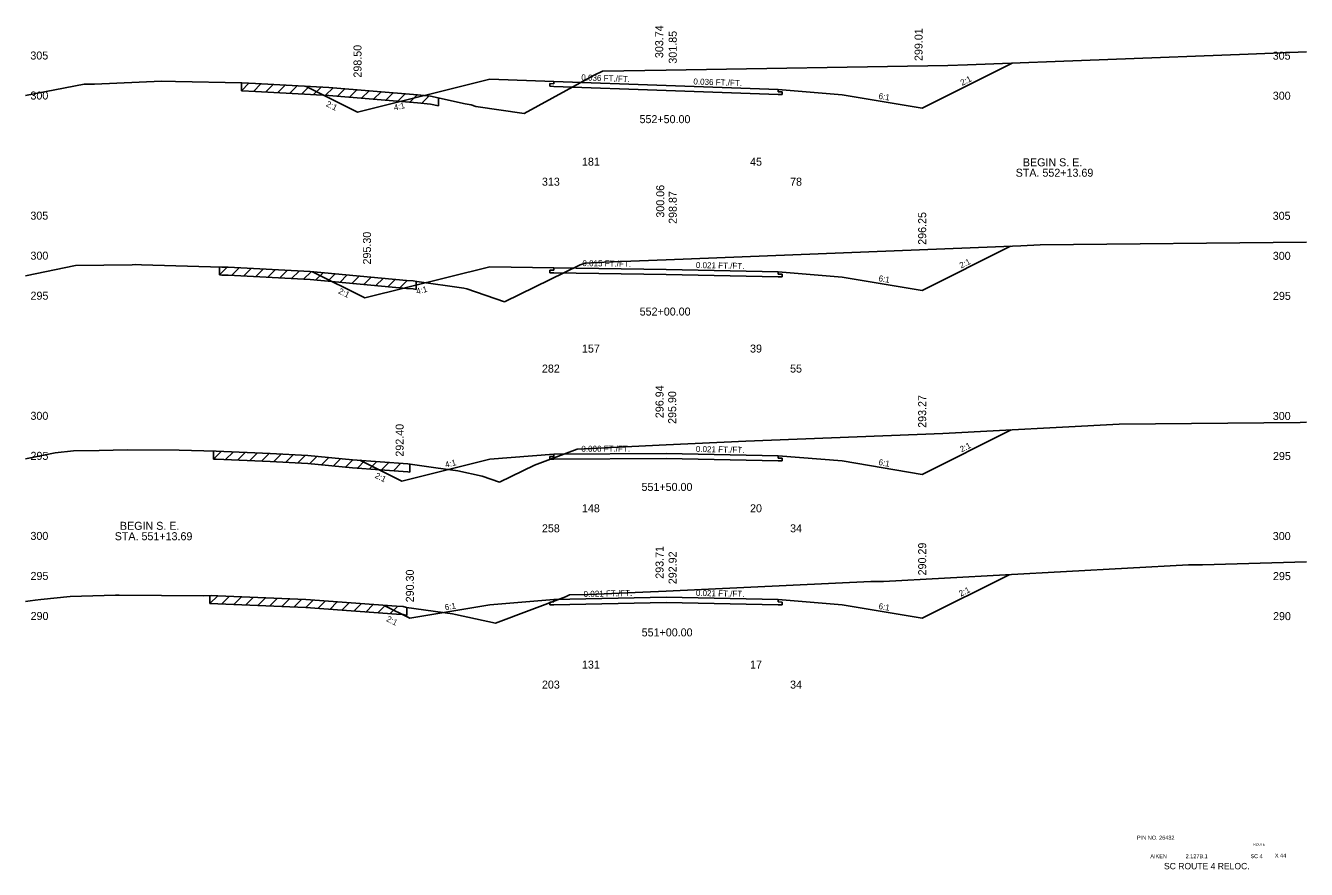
# Model space of a CAD drawing. Extents: x 2967 to 4323, y -3677 to -817.
# Drawn here: x 3555.3 to 3715.3, y -1510.9 to -1405.5 of the extents above; entities that cross this region are included whole.
import ezdxf

# ---------------------------------------------------------------- set-up
doc = ezdxf.new("R2010")
doc.units = 0
for name, color, linetype in [('Level 1', 7, 'Continuous'), ('Level 10', 7, 'Continuous'), ('Level 11', 7, 'Continuous'), ('Level 12', 7, 'Continuous'), ('Level 20', 7, 'Continuous'), ('Level 3', 7, 'Continuous'), ('Level 32', 7, 'Continuous'), ('Level 33', 7, 'Continuous'), ('Level 59', 7, 'Continuous'), ('Level 6', 7, 'Continuous'), ('Level 60', 7, 'Continuous'), ('Level 61', 7, 'Continuous'), ('Level 7', 7, 'Continuous')]:
    doc.layers.add(name, color=color, linetype=linetype)

msp = doc.modelspace()

# ---------------------------------------------------------------- linework, layer by layer
at = {"layer": 'Level 11'}
for p, q in [((3621.35, -1412.79), (3620.85, -1412.77)), ((3620.85, -1412.77), (3620.85, -1413.11)), ((3621.35, -1412.49), (3621.35, -1412.79)), ((3620.85, -1413.11), (3621.35, -1413.13)), ((3649.35, -1413.8), (3649.35, -1413.5)), ((3649.85, -1413.81), (3649.35, -1413.8)), ((3649.35, -1414.14), (3649.85, -1414.15)), ((3649.85, -1414.15), (3649.85, -1413.81)), ((3621.35, -1436.06), (3620.85, -1436.05)), ((3620.85, -1436.05), (3620.85, -1436.39)), ((3620.85, -1436.39), (3621.35, -1436.4)), ((3621.35, -1435.76), (3621.35, -1436.06)), ((3649.35, -1436.56), (3649.35, -1436.26)), ((3649.85, -1436.57), (3649.35, -1436.56)), ((3649.85, -1436.91), (3649.85, -1436.57)), ((3649.35, -1436.9), (3649.85, -1436.91)), ((3621.35, -1459.03), (3621.35, -1459.33)), ((3621.35, -1459.33), (3620.85, -1459.33)), ((3620.85, -1459.33), (3620.85, -1459.67)), ((3620.85, -1459.67), (3621.35, -1459.67)), ((3649.35, -1459.54), (3649.35, -1459.24)), ((3649.85, -1459.55), (3649.35, -1459.54)), ((3649.35, -1459.88), (3649.85, -1459.89)), ((3649.85, -1459.89), (3649.85, -1459.55)), ((3621.35, -1477.51), (3620.85, -1477.52)), ((3620.85, -1477.52), (3620.85, -1477.86)), ((3620.85, -1477.86), (3621.35, -1477.85)), ((3621.35, -1477.21), (3621.35, -1477.51)), ((3649.35, -1477.51), (3649.35, -1477.21)), ((3649.85, -1477.52), (3649.35, -1477.51)), ((3649.35, -1477.85), (3649.85, -1477.86)), ((3649.85, -1477.86), (3649.85, -1477.52))]:
    msp.add_line(p, q, dxfattribs=at)
at = {"layer": 'Level 12'}
for p, q in [((3635.35, -1413.63), (3621.35, -1413.13)), ((3649.35, -1414.14), (3635.35, -1413.63)), ((3635.35, -1436.61), (3621.35, -1436.4)), ((3649.35, -1436.9), (3635.35, -1436.61)), ((3635.35, -1459.59), (3621.35, -1459.67)), ((3649.35, -1459.88), (3635.35, -1459.59)), ((3635.35, -1477.56), (3621.35, -1477.85)), ((3649.35, -1477.85), (3635.35, -1477.56))]:
    msp.add_line(p, q, dxfattribs=at)
at = {"layer": 'Level 59'}
for p, q in [((3621.35, -1412.49), (3635.35, -1412.99)), ((3635.35, -1412.99), (3649.35, -1413.5)), ((3621.35, -1435.76), (3635.35, -1435.97)), ((3635.35, -1435.97), (3649.35, -1436.26)), ((3621.35, -1459.03), (3635.35, -1458.95)), ((3635.35, -1458.95), (3649.35, -1459.24)), ((3621.35, -1477.21), (3635.35, -1476.92)), ((3635.35, -1476.92), (3649.35, -1477.21))]:
    msp.add_line(p, q, dxfattribs=at)
at = {"layer": 'Level 6'}
for p, q in [((3613.35, -1412.2), (3621.35, -1412.49)), ((3649.35, -1413.5), (3657.35, -1414.16)), ((3613.35, -1435.64), (3621.35, -1435.76)), ((3649.35, -1436.26), (3657.35, -1436.93)), ((3613.35, -1459.69), (3621.35, -1459.03)), ((3649.35, -1459.24), (3657.35, -1459.9)), ((3613.35, -1477.88), (3621.35, -1477.21)), ((3649.35, -1477.21), (3657.35, -1477.88))]:
    msp.add_line(p, q, dxfattribs=at)
at = {"layer": 'Level 60'}
for p, q in [((3673.02, -1410.42), (3708.07, -1409.09)), ((3708.07, -1409.09), (3715.35, -1408.81)), ((3627.4, -1411.23), (3635.35, -1411.1)), ((3635.35, -1411.1), (3670.57, -1410.52)), ((3670.57, -1410.52), (3673.02, -1410.42)), ((3563.94, -1412.83), (3572.33, -1412.47)), ((3572.33, -1412.47), (3574.07, -1412.52)), ((3574.07, -1412.52), (3582.35, -1412.68)), ((3582.35, -1412.68), (3584.07, -1412.77)), ((3584.07, -1412.77), (3593.24, -1413.26)), ((3617.62, -1416.52), (3626.39, -1411.72)), ((3626.39, -1411.72), (3627.4, -1411.23)), ((3555.35, -1414.24), (3562.66, -1412.85)), ((3562.66, -1412.85), (3563.94, -1412.83)), ((3593.24, -1413.26), (3604.3, -1414.18)), ((3604.3, -1414.18), (3605.91, -1414.32)), ((3605.91, -1414.32), (3610.26, -1415.3)), ((3610.26, -1415.3), (3611.02, -1415.41)), ((3611.02, -1415.41), (3611.61, -1415.62)), ((3611.61, -1415.62), (3617.62, -1416.52)), ((3635.35, -1434.78), (3679.66, -1433.03)), ((3679.66, -1433.03), (3682.1, -1432.9)), ((3682.1, -1432.9), (3715.35, -1432.56)), ((3624.62, -1435.42), (3625.23, -1435.19)), ((3625.23, -1435.19), (3627.63, -1435.08)), ((3627.63, -1435.08), (3635.35, -1434.78)), ((3555.35, -1436.78), (3561.6, -1435.47)), ((3561.6, -1435.47), (3568.65, -1435.39)), ((3568.65, -1435.39), (3569.06, -1435.38)), ((3569.06, -1435.38), (3569.83, -1435.39)), ((3569.83, -1435.39), (3579.84, -1435.68)), ((3579.84, -1435.68), (3580.66, -1435.71)), ((3580.66, -1435.71), (3590.89, -1436.25)), ((3590.89, -1436.25), (3602.95, -1437.36)), ((3615.16, -1440.02), (3624.62, -1435.42)), ((3602.95, -1437.36), (3603.78, -1437.42)), ((3603.78, -1437.42), (3604.2, -1437.48)), ((3604.2, -1437.48), (3610.11, -1438.33)), ((3610.11, -1438.33), (3610.47, -1438.41)), ((3610.47, -1438.41), (3615.16, -1440.02)), ((3669.92, -1456.47), (3691.96, -1455.31)), ((3691.96, -1455.31), (3714.56, -1455.08)), ((3714.56, -1455.08), (3715.35, -1455.06)), ((3635.35, -1457.9), (3645.34, -1457.44)), ((3645.34, -1457.44), (3669.92, -1456.47)), ((3555.35, -1459.65), (3559.05, -1458.87)), ((3559.05, -1458.87), (3561.31, -1458.64)), ((3561.31, -1458.64), (3564.55, -1458.6)), ((3564.55, -1458.6), (3568.03, -1458.5)), ((3568.03, -1458.5), (3574.52, -1458.55)), ((3574.52, -1458.55), (3579.14, -1458.68)), ((3579.14, -1458.68), (3585.88, -1458.98)), ((3585.88, -1458.98), (3590.6, -1459.23)), ((3618.92, -1460.42), (3624.26, -1458.41)), ((3624.26, -1458.41), (3635.35, -1457.9)), ((3590.6, -1459.23), (3596.17, -1459.74)), ((3596.17, -1459.74), (3603.1, -1460.26)), ((3603.1, -1460.26), (3606.6, -1460.75)), ((3606.6, -1460.75), (3609.33, -1461.14)), ((3614.55, -1462.54), (3618.92, -1460.42)), ((3609.33, -1461.14), (3612.38, -1461.8)), ((3612.38, -1461.8), (3614.55, -1462.54)), ((3662.5, -1474.96), (3700.62, -1472.89)), ((3700.62, -1472.89), (3702.37, -1472.89)), ((3702.37, -1472.89), (3715.35, -1472.5)), ((3635.35, -1476.14), (3660.92, -1474.95)), ((3660.92, -1474.95), (3662.5, -1474.96)), ((3560.92, -1476.83), (3566.56, -1476.65)), ((3566.56, -1476.65), (3567.04, -1476.65)), ((3567.04, -1476.65), (3577.62, -1476.73)), ((3577.62, -1476.73), (3578.53, -1476.72)), ((3578.53, -1476.72), (3579.38, -1476.73)), ((3579.38, -1476.73), (3590.35, -1477.21)), ((3622.78, -1476.87), (3623.29, -1476.63)), ((3623.29, -1476.63), (3625.67, -1476.58)), ((3625.67, -1476.58), (3635.35, -1476.14)), ((3555.35, -1477.46), (3555.9, -1477.36)), ((3555.9, -1477.36), (3556.54, -1477.3)), ((3556.54, -1477.3), (3557.26, -1477.2)), ((3557.26, -1477.2), (3560.92, -1476.83)), ((3590.35, -1477.21), (3601.68, -1478.05)), ((3601.68, -1478.05), (3602.51, -1478.09)), ((3602.51, -1478.09), (3602.94, -1478.2)), ((3602.94, -1478.2), (3608.66, -1479)), ((3614.04, -1480.17), (3622.78, -1476.87)), ((3608.66, -1479), (3609.07, -1479.09)), ((3609.07, -1479.09), (3614.04, -1480.17))]:
    msp.add_line(p, q, dxfattribs=at)
at = {"layer": 'Level 61'}
for p, q in [((3582.3, -1412.68), (3582.3, -1413.68)), ((3583.25, -1412.73), (3582.3, -1413.68)), ((3582.3, -1413.68), (3582.35, -1413.68)), ((3582.35, -1413.68), (3584.07, -1413.77)), ((3584.75, -1412.8), (3583.8, -1413.75)), ((3584.07, -1413.77), (3593.24, -1414.26)), ((3586.26, -1412.88), (3585.3, -1413.83)), ((3587.76, -1412.96), (3586.81, -1413.91)), ((3589.26, -1413.04), (3588.31, -1413.99)), ((3590.76, -1413.12), (3589.81, -1414.07)), ((3592.26, -1413.2), (3591.31, -1414.15)), ((3593.75, -1413.3), (3592.82, -1414.23)), ((3593.24, -1414.26), (3604.3, -1415.18)), ((3595.24, -1413.42), (3594.32, -1414.34)), ((3596.74, -1413.55), (3595.82, -1414.47)), ((3598.25, -1413.67), (3597.32, -1414.59)), ((3599.75, -1413.8), (3598.82, -1414.72)), ((3601.25, -1413.92), (3600.33, -1414.85)), ((3602.75, -1414.05), (3601.83, -1414.97)), ((3604.26, -1414.17), (3603.33, -1415.1)), ((3605.75, -1414.31), (3604.83, -1415.22)), ((3604.3, -1415.18), (3605.91, -1415.32)), ((3605.91, -1415.32), (3606.91, -1415.55)), ((3606.91, -1415.55), (3606.91, -1414.55)), ((3579.56, -1435.67), (3579.56, -1436.67)), ((3580.53, -1435.71), (3579.56, -1436.67)), ((3579.56, -1436.67), (3579.84, -1436.68)), ((3579.84, -1436.68), (3580.66, -1436.71)), ((3580.66, -1436.71), (3590.89, -1437.25)), ((3582.02, -1435.78), (3581.07, -1436.73)), ((3583.52, -1435.86), (3582.57, -1436.81)), ((3585.02, -1435.94), (3584.07, -1436.89)), ((3586.53, -1436.02), (3585.57, -1436.97)), ((3588.03, -1436.1), (3587.08, -1437.05)), ((3589.53, -1436.18), (3588.58, -1437.13)), ((3591.03, -1436.26), (3590.08, -1437.21)), ((3592.5, -1436.4), (3591.58, -1437.31)), ((3594, -1436.53), (3593.09, -1437.45)), ((3595.5, -1436.67), (3594.59, -1437.59)), ((3590.89, -1437.25), (3602.95, -1438.36)), ((3597.01, -1436.81), (3596.09, -1437.73)), ((3598.51, -1436.95), (3597.59, -1437.86)), ((3600.01, -1437.09), (3599.09, -1438)), ((3601.51, -1437.22), (3600.6, -1438.14)), ((3603.02, -1437.36), (3602.1, -1438.28)), ((3602.95, -1438.36), (3603.78, -1438.42)), ((3604.13, -1438.47), (3604.13, -1437.47)), ((3603.78, -1438.42), (3604.13, -1438.47)), ((3578.81, -1458.67), (3578.81, -1459.67)), ((3579.77, -1458.71), (3578.81, -1459.67)), ((3581.27, -1458.78), (3580.31, -1459.73)), ((3582.77, -1458.84), (3581.81, -1459.8)), ((3584.27, -1458.91), (3583.31, -1459.87)), ((3585.77, -1458.98), (3584.81, -1459.93)), ((3587.26, -1459.05), (3586.31, -1460)), ((3588.76, -1459.13), (3587.81, -1460.08)), ((3578.81, -1459.67), (3579.14, -1459.68)), ((3579.14, -1459.68), (3585.88, -1459.98)), ((3585.88, -1459.98), (3590.6, -1460.23)), ((3590.26, -1459.21), (3589.31, -1460.16)), ((3590.6, -1460.23), (3596.17, -1460.74)), ((3591.72, -1459.33), (3590.81, -1460.25)), ((3593.22, -1459.47), (3592.31, -1460.38)), ((3594.72, -1459.61), (3593.81, -1460.52)), ((3596.22, -1459.74), (3595.31, -1460.66)), ((3596.17, -1460.74), (3603.1, -1461.26)), ((3597.74, -1459.86), (3596.81, -1460.79)), ((3599.24, -1459.97), (3598.31, -1460.9)), ((3600.74, -1460.08), (3599.81, -1461.01)), ((3602.24, -1460.19), (3601.31, -1461.12)), ((3603.35, -1461.29), (3603.35, -1460.29)), ((3603.1, -1461.26), (3603.35, -1461.29)), ((3578.35, -1476.72), (3578.35, -1477.72)), ((3579.34, -1476.73), (3578.35, -1477.72)), ((3580.81, -1476.79), (3579.85, -1477.75)), ((3578.35, -1477.72), (3578.53, -1477.72)), ((3578.53, -1477.72), (3579.38, -1477.73)), ((3579.38, -1477.73), (3590.35, -1478.21)), ((3582.31, -1476.86), (3581.35, -1477.81)), ((3583.81, -1476.92), (3582.85, -1477.88)), ((3585.31, -1476.99), (3584.35, -1477.95)), ((3586.81, -1477.05), (3585.85, -1478.01)), ((3588.31, -1477.12), (3587.35, -1478.08)), ((3589.81, -1477.19), (3588.85, -1478.14)), ((3591.28, -1477.28), (3590.35, -1478.21)), ((3590.35, -1478.21), (3601.68, -1479.05)), ((3592.78, -1477.39), (3591.85, -1478.32)), ((3594.28, -1477.5), (3593.35, -1478.43)), ((3595.78, -1477.61), (3594.85, -1478.54)), ((3597.28, -1477.73), (3596.35, -1478.66)), ((3598.78, -1477.84), (3597.85, -1478.77)), ((3600.28, -1477.95), (3599.35, -1478.88)), ((3601.79, -1478.06), (3600.85, -1478.99)), ((3602.98, -1479.2), (3602.98, -1478.2)), ((3601.68, -1479.05), (3602.51, -1479.09)), ((3602.51, -1479.09), (3602.94, -1479.2)), ((3602.94, -1479.2), (3602.98, -1479.2))]:
    msp.add_line(p, q, dxfattribs=at)
at = {"layer": 'Level 7'}
for p, q in [((3667.35, -1415.83), (3678.59, -1410.21)), ((3613.35, -1412.2), (3596.79, -1416.34)), ((3596.79, -1416.34), (3590.31, -1413.1)), ((3657.35, -1414.16), (3667.35, -1415.83)), ((3667.35, -1438.59), (3678.37, -1433.08)), ((3597.73, -1439.54), (3591.2, -1436.28)), ((3613.35, -1435.64), (3597.73, -1439.54)), ((3657.35, -1436.93), (3667.35, -1438.59)), ((3667.35, -1461.57), (3678.45, -1456.02)), ((3597.1, -1459.81), (3602.36, -1462.44)), ((3613.35, -1459.69), (3602.36, -1462.44)), ((3657.35, -1459.9), (3667.35, -1461.57)), ((3667.35, -1479.55), (3678.23, -1474.11)), ((3600.13, -1477.94), (3603.35, -1479.55)), ((3603.35, -1479.55), (3613.35, -1477.88)), ((3657.35, -1477.88), (3667.35, -1479.55))]:
    msp.add_line(p, q, dxfattribs=at)

# ---------------------------------------------------------------- texts
at = {"layer": 'Level 1'}
for s, p in [('181', (3624.85, -1423.02)), ('45', (3645.85, -1423.02)), ('BEGIN S. E.', (3679.93, -1423.1)), ('STA. 552+13.69', (3679.03, -1424.4)), ('313', (3619.85, -1425.52)), ('78', (3650.85, -1425.52)), ('157', (3624.85, -1446.36)), ('39', (3645.85, -1446.36)), ('282', (3619.85, -1448.86)), ('55', (3650.85, -1448.86)), ('148', (3624.85, -1466.31)), ('20', (3645.85, -1466.31)), ('STA. 551+13.69', (3566.48, -1469.8)), ('BEGIN S. E.', (3567.13, -1468.5)), ('258', (3619.85, -1468.81)), ('34', (3650.85, -1468.81)), ('131', (3624.85, -1485.83)), ('17', (3645.85, -1485.83)), ('203', (3619.85, -1488.33)), ('34', (3650.85, -1488.33))]:
    msp.add_text(s, height=1, dxfattribs=at).set_placement(p)
at = {"layer": 'Level 10'}
for s, p in [('303.74', (3635, -1409.58)), ('300.06', (3635.13, -1429.51)), ('296.94', (3635.04, -1454.55)), ('293.71', (3635.04, -1474.61))]:
    msp.add_text(s, height=1, rotation=90, dxfattribs=at).set_placement(p)
for s, p in [('552+50.00', (3632.04, -1417.71)), ('552+00.00', (3632.06, -1441.74)), ('551+50.00', (3632.29, -1463.64)), ('551+00.00', (3632.31, -1481.81))]:
    msp.add_text(s, height=1, dxfattribs=at).set_placement(p)
at = {"layer": 'Level 20'}
for s, height, p in [('PIN NO. 26432', 0.5, (3694.19, -1507.2)), ('ROUTE', 0.3, (3708.73, -1507.94)), ('AIKEN', 0.5, (3695.85, -1509.51)), ('SC ROUTE 4 RELOC.', 0.8, (3697.56, -1510.9)), (' 2.127B.1', 0.5, (3700.07, -1509.51)), ('SC 4', 0.5, (3708.36, -1509.51)), ('X 44', 0.5, (3711.41, -1509.43))]:
    msp.add_text(s, height=height, dxfattribs=at).set_placement(p)
at = {"layer": 'Level 3'}
for s, p in [(' 305', (3555.57, -1409.76)), (' 305', (3710.77, -1409.78)), (' 300', (3555.58, -1414.76)), (' 300', (3710.78, -1414.78)), (' 305', (3555.57, -1429.76)), (' 305', (3710.77, -1429.78)), (' 300', (3555.58, -1434.76)), (' 300', (3710.78, -1434.78)), (' 295', (3555.59, -1439.76)), (' 295', (3710.8, -1439.78)), (' 300', (3555.58, -1454.76)), (' 300', (3710.78, -1454.78)), (' 295', (3555.59, -1459.76)), (' 295', (3710.8, -1459.78)), (' 300', (3555.58, -1469.76)), (' 300', (3710.78, -1469.78)), (' 295', (3555.59, -1474.76)), (' 295', (3710.8, -1474.78)), (' 290', (3555.6, -1479.76)), (' 290', (3710.81, -1479.78))]:
    msp.add_text(s, height=1, dxfattribs=at).set_placement(p)
at = {"layer": 'Level 32'}
for s, rotation, p in [('0.036 FT./FT.', 357.9396, (3624.76, -1412.36)), ('0.036 FT./FT.', 357.9418, (3638.76, -1412.87)), ('2:1', 26.5651, (3672.35, -1413.05)), ('6:1', 350.5377, (3661.86, -1414.66)), ('2:1', 333.435, (3592.8, -1415.56)), ('4:1', 14.0362, (3601.44, -1416.15)), ('0.015 FT./FT.', 359.132, (3624.9, -1435.56)), ('0.021 FT./FT.', 358.8084, (3639.07, -1435.8)), ('2:1', 26.5651, (3672.24, -1435.87)), ('6:1', 350.5377, (3661.86, -1437.43)), ('2:1', 333.435, (3594.34, -1438.93)), ('4:1', 14.0362, (3604.24, -1439.1)), ('0.006 FT./FT.', 0.3252, (3624.78, -1458.76)), ('0.021 FT./FT.', 358.8084, (3639.07, -1458.77)), ('2:1', 26.5651, (3672.28, -1458.83)), ('4:1', 14.0362, (3607.84, -1460.75)), ('6:1', 350.5377, (3661.86, -1460.4)), ('2:1', 333.435, (3598.91, -1461.97)), ('0.021 FT./FT.', 1.1916, (3625.06, -1476.89)), ('0.021 FT./FT.', 358.8084, (3639.07, -1476.75)), ('2:1', 26.5651, (3672.17, -1476.86)), ('6:1', 9.4623, (3607.78, -1478.55)), ('6:1', 350.5377, (3661.86, -1478.38)), ('2:1', 333.435, (3600.34, -1479.87))]:
    msp.add_text(s, height=0.75, rotation=rotation, dxfattribs=at).set_placement(p)
at = {"layer": 'Level 33'}
for s, p in [('299.01', (3667.4, -1409.95)), ('298.50', (3597.31, -1412.02)), ('296.25', (3667.85, -1432.9)), ('295.30', (3598.49, -1435.36)), ('293.27', (3667.85, -1455.76)), ('292.40', (3602.57, -1459.36)), ('290.29', (3667.85, -1474.19)), ('290.30', (3603.85, -1477.55))]:
    msp.add_text(s, height=1, rotation=90, dxfattribs=at).set_placement(p)
at = {"layer": 'Level 59'}
for s, p in [(' 301.85', (3636.69, -1410.65)), (' 298.87', (3636.69, -1430.66)), (' 295.90', (3636.62, -1455.64)), (' 292.92', (3636.67, -1475.66))]:
    msp.add_text(s, height=1, rotation=90, dxfattribs=at).set_placement(p)

doc.saveas('drawing.dxf')
